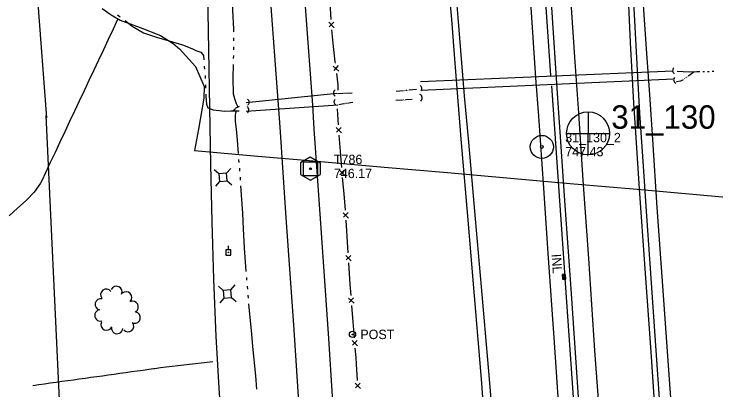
# Model space of a CAD drawing. Extents: x 589250 to 1188077, y 162953 to 363065.
# Drawn here: x 593773.6 to 594223.8, y 172497 to 172737.9 of the extents above; entities that cross this region are included whole.
import ezdxf

# ---------------------------------------------------------------- set-up
doc = ezdxf.new("R2010")
doc.units = 0
for name, color, linetype in [('E_DRN', 7, 'Continuous'), ('E_DRN_DrainTile', 7, 'Continuous'), ('E_DRN_Pipe', 7, 'Continuous'), ('E_DRN_SS_UG', 7, 'Continuous'), ('E_DRN_Text', 7, 'Continuous'), ('E_FEN_P', 7, 'Continuous'), ('E_LAND_TreeLine_P', 7, 'Continuous'), ('E_MAP_Control', 7, 'Continuous'), ('E_MAP_Limits', 7, 'Continuous'), ('E_MAP_PassPoints', 7, 'Continuous'), ('E_MAP_PhotoCenter', 7, 'Continuous'), ('E_MISCPROP', 7, 'Continuous'), ('E_RDWY', 7, 'Continuous'), ('E_RDWY_Gravel', 7, 'Continuous'), ('E_UTL_AG_Bold', 7, 'Continuous'), ('E_UTL_EPowerPole', 7, 'Continuous'), ('E_WAL', 7, 'Continuous'), ('E_WTR_FlowLine', 7, 'Continuous')]:
    doc.layers.add(name, color=color, linetype=linetype)

msp = doc.modelspace()

# ---------------------------------------------------------------- linework, layer by layer
at = {"layer": 'E_DRN'}
for p, q in [((594127.19, 172571.11), (594125.2, 172570.98)), ((594125.2, 172570.98), (594125.39, 172567.99)), ((594125.26, 172569.99), (594127.26, 172570.11)), ((594126.39, 172568.05), (594126.19, 172571.05)), ((594127.38, 172568.12), (594127.19, 172571.11)), ((594125.32, 172568.99), (594127.32, 172569.12)), ((594125.39, 172567.99), (594127.38, 172568.12))]:
    msp.add_line(p, q, dxfattribs=at)
for centre, radius, start, end in [((594198.32, 172701.63), 2.34, 131.1922, 237.4524), ((594198.89, 172695.73), 2.27, 141.862, 248.1222), ((594033.01, 172690.17), 2.09, 316.5719, 62.8321), ((593980.99, 172687.34), 2.54, 127.8258, 234.086), ((593921.97, 172681.39), 2.38, 307.8258, 54.086), ((593980.8, 172681.59), 2.07, 132.2245, 238.4847), ((594032.61, 172684.07), 2.72, 314.5356, 60.7958), ((593921.8, 172676.47), 2.38, 311.6398, 57.9)]:
    msp.add_arc(centre, radius, start, end, dxfattribs=at)
at = {"layer": 'E_DRN_DrainTile'}
for points in [[(593897.72, 172751.54), (593898.36, 172714.83), (593898.93, 172678.11), (593899.54, 172641.39), (593900.34, 172604.68), (593901.46, 172567.99), (593903.04, 172531.34), (593905.22, 172494.73), (593906.8, 172473.69), (593908.07, 172458.17), (593911.04, 172421.61), (593914.01, 172385.06), (593916.99, 172348.5), (593919.96, 172311.94), (593922.93, 172275.39), (593925.91, 172238.83), (593928.88, 172202.28)], [(593830.1, 172741.37), (593835.95, 172737.31), (593841.72, 172734.01), (593854.48, 172729.18), (593867.49, 172724.11), (593875.56, 172719.02), (593879.65, 172715.58), (593889.87, 172704.25), (593895.41, 172691.4), (593895.37, 172683.98), (593894.25, 172677.8), (593891.77, 172664.13), (593889.28, 172650.45), (593889.28, 172650.45), (593889.28, 172650.45)], [(593840.14, 172734.74), (593837.04, 172728.16), (593833.95, 172721.59), (593830.85, 172715.01), (593827.76, 172708.44), (593824.66, 172701.86), (593821.57, 172695.29), (593818.48, 172688.71), (593815.38, 172682.13), (593812.29, 172675.56), (593809.19, 172668.98), (593806.1, 172662.41), (593803, 172655.83), (593799.91, 172649.26), (593796.82, 172642.68), (593793.72, 172636.11), (593791.37, 172631.12), (593790.58, 172629.56), (593786.45, 172623.68), (593781.34, 172618.44), (593775.8, 172613.52), (593770.36, 172608.57)], [(593840.14, 172734.74), (593837.04, 172728.16), (593833.95, 172721.59), (593830.85, 172715.01), (593827.76, 172708.44), (593824.66, 172701.86), (593821.57, 172695.29), (593818.48, 172688.71), (593815.38, 172682.13), (593812.29, 172675.56), (593809.19, 172668.98), (593806.1, 172662.41), (593803, 172655.83), (593799.91, 172649.26), (593796.82, 172642.68), (593793.72, 172636.11), (593791.37, 172631.12), (593790.58, 172629.56), (593786.45, 172623.68), (593781.34, 172618.44), (593775.8, 172613.52), (593770.36, 172608.57)], [(593889.28, 172650.45), (593929.83, 172646.9), (593970.38, 172643.35), (594010.93, 172639.81), (594051.48, 172636.26), (594092.03, 172632.71), (594132.58, 172629.16), (594173.13, 172625.61), (594213.68, 172622.07), (594254.23, 172618.52), (594294.78, 172614.97), (594335.33, 172611.42), (594375.88, 172607.87), (594416.43, 172604.33), (594452.4, 172601.18), (594456.95, 172600.68), (594494.43, 172588.87), (594528.02, 172566.6), (594559.18, 172537.96)], [(593889.28, 172650.45), (593929.83, 172646.9), (593970.38, 172643.35), (594010.93, 172639.81), (594051.48, 172636.26), (594092.03, 172632.71), (594132.58, 172629.16), (594173.13, 172625.61), (594213.68, 172622.07), (594254.23, 172618.52), (594294.78, 172614.97), (594335.33, 172611.42), (594375.88, 172607.87), (594416.43, 172604.33), (594452.4, 172601.18), (594456.95, 172600.68), (594494.43, 172588.87), (594528.02, 172566.6), (594559.18, 172537.96)], [(593785.65, 172499.99), (593789.37, 172500.51), (593793.09, 172501.02), (593796.81, 172501.54), (593800.53, 172502.06), (593804.25, 172502.57), (593807.97, 172503.09), (593811.69, 172503.61), (593815.41, 172504.13), (593819.13, 172504.64), (593822.85, 172505.16), (593826.57, 172505.68), (593830.29, 172506.19), (593834.01, 172506.71), (593837.73, 172507.23), (593841.45, 172507.74), (593845.17, 172508.26), (593848.89, 172508.78), (593852.62, 172509.29), (593856.34, 172509.81), (593860.06, 172510.33), (593862.99, 172510.74), (593863.79, 172510.84), (593867.52, 172511.34), (593871.24, 172511.82), (593874.97, 172512.28), (593878.7, 172512.72), (593882.43, 172513.16), (593886.16, 172513.58), (593889.9, 172514.01), (593893.63, 172514.43), (593897.36, 172514.87), (593901.09, 172515.31), (593901.09, 172515.31), (593901.09, 172515.31)]]:
    msp.add_lwpolyline(points, dxfattribs=at)
at = {"layer": 'E_DRN_Pipe'}
for p, q in [((594117.95, 172698.49), (594099.27, 172967.03)), ((594034.19, 172694.63), (594196.39, 172701.51)), ((594196.66, 172696.18), (594034.43, 172688.97)), ((593922.5, 172681.23), (593980.52, 172687.25)), ((593922.54, 172675.76), (593981.32, 172679.71)), ((594147.67, 172271.34), (594126.99, 172568.64))]:
    msp.add_line(p, q, dxfattribs=at)
msp.add_lwpolyline([(594163.21, 172899.17), (594166.48, 172833.15), (594167.75, 172807.22), (594168.84, 172784.41), (594170.33, 172757.55), (594171.64, 172729.6), (594173.17, 172701.66), (594174.76, 172674.39), (594177.1, 172640.49), (594178.95, 172611.66), (594181.35, 172577.92), (594185.75, 172513.06), (594188.07, 172482.37), (594189.42, 172460.9)], dxfattribs=at)
at = {"layer": 'E_DRN_SS_UG'}
msp.add_line((594126.94, 172569.34), (594118.41, 172691.87), dxfattribs=at)
at = {"layer": 'E_FEN_P'}
for p, q in [((593976.02, 172745.13), (593976.75, 172734.41)), ((593975.37, 172732.66), (593978.88, 172729.15)), ((593978.63, 172732.71), (593975.64, 172729.68)), ((593977.21, 172727.78), (593977.5, 172723.56)), ((593977.5, 172723.56), (593978.25, 172717.08)), ((593978.25, 172717.08), (593979.38, 172707.28)), ((593979.38, 172707.28), (593979.49, 172706.41)), ((593978.2, 172704.58), (593981.9, 172701.27)), ((593981.45, 172704.82), (593978.64, 172701.63)), ((593980.31, 172699.81), (593981.23, 172692.46)), ((593981.23, 172692.46), (593981.29, 172689.12)), ((593980.75, 172677.24), (593981.49, 172666.82)), ((593980.15, 172665.11), (593983.57, 172661.7)), ((593983.32, 172665.17), (593980.42, 172662.22)), ((593981.95, 172660.36), (593982.7, 172649.94)), ((593982.7, 172649.94), (593983.09, 172644.41)), ((593983.09, 172644.41), (593983.52, 172639.52)), ((593982.21, 172637.79), (593985.68, 172634.44)), ((593985.38, 172637.9), (593982.53, 172634.9)), ((593984.09, 172633.08), (593985.01, 172622.67)), ((593985.01, 172622.67), (593985.93, 172612.26)), ((593984.61, 172610.53), (593988.09, 172607.18)), ((593987.78, 172610.64), (593984.93, 172607.64)), ((593986.44, 172605.81), (593987.08, 172595.38)), ((593987.08, 172595.38), (593987.71, 172584.95)), ((593986.34, 172583.25), (593989.73, 172579.81)), ((593989.52, 172583.28), (593986.58, 172580.36)), ((593988.1, 172578.49), (593988.73, 172568.06)), ((593988.73, 172568.06), (593988.93, 172564.77)), ((593988.93, 172564.77), (593989.5, 172557.63)), ((593988.17, 172555.91), (593991.62, 172552.54)), ((593991.35, 172556), (593988.47, 172553.02)), ((593990.02, 172551.19), (593990.86, 172540.77)), ((593990.86, 172540.77), (593991.7, 172530.35)), ((593990.37, 172528.63), (593993.82, 172525.26)), ((593993.54, 172528.72), (593990.67, 172525.74)), ((593992.22, 172523.9), (593992.71, 172517.81)), ((593992.71, 172517.81), (593993, 172513.48)), ((593993, 172513.48), (593993.72, 172503.05)), ((593992.36, 172501.35), (593995.78, 172497.93)), ((593995.54, 172501.4), (593992.63, 172498.46))]:
    msp.add_line(p, q, dxfattribs=at)
at = {"layer": 'E_LAND_TreeLine_P'}
for centre, start, end in [((593832.72, 172558), 36.8561, 216.8561), ((593839.23, 172559.88), 336.1583, 156.1583), ((593845.47, 172556.35), 313.8665, 133.8665), ((593829.24, 172551.81), 76.566, 256.566), ((593849.65, 172550.26), 297.1673, 117.1673), ((593829, 172544.75), 104.6385, 284.6385), ((593850.92, 172543.36), 259.2923, 79.2923), ((593832.89, 172538.92), 156.3745, 336.3745), ((593846.73, 172537.87), 220.0747, 40.0747), ((593839.73, 172536.7), 175.4078, 355.4078)]:
    msp.add_arc(centre, 3.64, start, end, dxfattribs=at)
at = {"layer": 'E_MAP_Control'}
for p, q in [((593959.18, 172634.27), (593959.18, 172643.27)), ((593959.18, 172643.27), (593968.18, 172643.27)), ((593959.18, 172634.27), (593959.18, 172643.27)), ((593959.18, 172643.27), (593968.18, 172643.27)), ((593968.18, 172643.27), (593968.18, 172634.27)), ((593968.18, 172643.27), (593968.18, 172634.27)), ((593968.18, 172634.27), (593959.18, 172634.27)), ((593968.18, 172634.27), (593959.18, 172634.27))]:
    msp.add_line(p, q, dxfattribs=at)
msp.add_lwpolyline([(593957.27, 172642.53), (593957.27, 172635.14), (593963.73, 172631.42), (593970.12, 172635.08), (593970.12, 172642.41), (593963.6, 172646.13)], close=True, dxfattribs=at)
msp.add_lwpolyline([(593957.27, 172642.53), (593957.27, 172635.14), (593963.73, 172631.42), (593970.12, 172635.08), (593970.12, 172642.41), (593963.6, 172646.13)], close=True, dxfattribs=at)
msp.add_circle((593963.68, 172638.77), 0.546, dxfattribs=at)
msp.add_circle((593963.68, 172638.77), 0.546, dxfattribs=at)
at = {"layer": 'E_MAP_Limits'}
for p, q in [((593788.54, 172747.67), (593794.28, 172671.36)), ((593809.24, 172353.09), (593794.17, 172672.82))]:
    msp.add_line(p, q, dxfattribs=at)
at = {"layer": 'E_MAP_PassPoints'}
for radius in [7.38, 7.38, 0.945, 0.945]:
    msp.add_circle((594112.08, 172652.77), radius, dxfattribs=at)
at = {"layer": 'E_MAP_PhotoCenter'}
for p, q in [((594141.72, 172675.22), (594141.65, 172647.81)), ((594141.72, 172675.22), (594141.65, 172647.81)), ((594128.03, 172661.41), (594155.49, 172661.4)), ((594128.03, 172661.41), (594155.49, 172661.4))]:
    msp.add_line(p, q, dxfattribs=at)
msp.add_circle((594141.77, 172661.42), 13.78, dxfattribs=at)
msp.add_circle((594141.77, 172661.42), 13.78, dxfattribs=at)
at = {"layer": 'E_MISCPROP'}
for radius in [2, 0.25]:
    msp.add_circle((593990.66, 172532.63), radius, dxfattribs=at)
at = {"layer": 'E_RDWY'}
for p, q in [((594052.77, 172797.07), (594058.17, 172735.71)), ((593958.7, 172764.44), (593962.07, 172719.65)), ((594166.65, 172762.38), (594168.81, 172719.74)), ((593937.54, 172753.91), (593941.15, 172705.31)), ((594104.55, 172749.92), (594108.09, 172696.97)), ((594130.19, 172752.45), (594133.09, 172710.31)), ((594058.17, 172735.71), (594062.29, 172685.58)), ((593962.07, 172719.65), (593965, 172679.56)), ((594168.81, 172719.74), (594170.92, 172680.85)), ((594133.09, 172710.31), (594135.61, 172674.34)), ((593941.15, 172705.31), (593943.97, 172665.31)), ((594108.09, 172696.97), (594109.91, 172672.47)), ((594062.29, 172685.58), (594064.98, 172655.75)), ((593965, 172679.56), (593965.95, 172664.39)), ((594170.92, 172680.85), (594172.2, 172661.96)), ((594135.61, 172674.34), (594138.45, 172631.53)), ((594109.91, 172672.47), (594113.21, 172626.32)), ((593943.97, 172665.31), (593947.99, 172607.25)), ((593965.95, 172664.39), (593970.15, 172603.69)), ((594172.2, 172661.96), (594174.52, 172625.81)), ((594064.98, 172655.75), (594069.23, 172606.68)), ((594138.45, 172631.53), (594141.98, 172581.25)), ((594113.21, 172626.32), (594116.03, 172584.77)), ((594174.52, 172625.81), (594178.23, 172574.59)), ((593947.99, 172607.25), (593952.7, 172538.72)), ((594069.23, 172606.68), (594073.09, 172563.02)), ((593970.15, 172603.69), (593975.17, 172529.92)), ((594116.03, 172584.77), (594119.96, 172527.51)), ((594141.98, 172581.25), (594145.93, 172522.41)), ((594178.23, 172574.59), (594181.99, 172521.46)), ((594073.09, 172563.02), (594077.76, 172511.48)), ((593952.7, 172538.72), (593957.43, 172468.93)), ((593975.17, 172529.92), (593981.09, 172440.94)), ((594119.96, 172527.51), (594123.35, 172476.44)), ((594145.93, 172522.41), (594148.46, 172487.84)), ((594181.99, 172521.46), (594185.37, 172472.13)), ((594077.76, 172511.48), (594082.45, 172456.36))]:
    msp.add_line(p, q, dxfattribs=at)
at = {"layer": 'E_RDWY_Gravel'}
for p, q in [((594051.2, 172767.83), (594054.07, 172734.33)), ((594176.86, 172746.68), (594179, 172715.65)), ((594054.07, 172734.33), (594056.35, 172706.36)), ((594179, 172715.65), (594181.09, 172686.25)), ((594056.35, 172706.36), (594058.59, 172676.7)), ((594181.09, 172686.25), (594182.98, 172657.59)), ((594058.59, 172676.7), (594060.31, 172655.15)), ((594060.29, 172655.39), (594064.41, 172608.3)), ((594182.98, 172657.59), (594185.75, 172613.84)), ((594185.75, 172613.84), (594189.99, 172557.7)), ((594064.41, 172608.3), (594068.6, 172557.39)), ((594068.6, 172557.39), (594073.31, 172501.42)), ((594189.99, 172557.7), (594194.84, 172488.87)), ((594073.31, 172501.42), (594077.16, 172452.26))]:
    msp.add_line(p, q, dxfattribs=at)
at = {"layer": 'E_UTL_AG_Bold'}
for p, q in [((593904.93, 172635.55), (593901.89, 172638.15)), ((593909.92, 172635.94), (593912.52, 172638.98)), ((593909.92, 172635.94), (593904.93, 172635.55)), ((593904.93, 172635.55), (593905.32, 172630.57)), ((593910.31, 172630.96), (593909.92, 172635.94)), ((593905.32, 172630.57), (593902.72, 172627.53)), ((593905.32, 172630.57), (593910.31, 172630.96)), ((593910.31, 172630.96), (593913.35, 172628.36)), ((593907.71, 172560.86), (593904.67, 172563.46)), ((593912.69, 172561.25), (593907.71, 172560.86)), ((593907.71, 172560.86), (593908.1, 172555.88)), ((593912.69, 172561.25), (593915.29, 172564.29)), ((593913.08, 172556.27), (593912.69, 172561.25)), ((593908.1, 172555.88), (593905.5, 172552.84)), ((593908.1, 172555.88), (593913.08, 172556.27)), ((593913.08, 172556.27), (593916.12, 172553.67))]:
    msp.add_line(p, q, dxfattribs=at)
at = {"layer": 'E_UTL_EPowerPole'}
for points in [[(593911.02, 172586.84), (593911.02, 172589.48)], [(593912.69, 172586.84), (593909.34, 172586.84)], [(593909.34, 172586.84), (593909.34, 172583.48)], [(593909.34, 172583.48), (593912.69, 172583.48)], [(593912.69, 172583.48), (593912.69, 172586.84)]]:
    msp.add_lwpolyline(points, dxfattribs=at)
msp.add_circle((593911.05, 172585.16), 0.217, dxfattribs=at)
at = {"layer": 'E_WAL'}
for p, q in [((594116.59, 172766.21), (594121.38, 172696.7)), ((594121.38, 172696.7), (594123.26, 172668.29)), ((594123.24, 172668.55), (594126.73, 172615.21)), ((594126.73, 172615.21), (594130.78, 172561.83)), ((594130.78, 172561.83), (594136.11, 172481.46))]:
    msp.add_line(p, q, dxfattribs=at)
at = {"layer": 'E_WTR_FlowLine'}
for p, q in [((593912.83, 172754.11), (593914.37, 172728.22)), ((593839.94, 172737.32), (593841.54, 172736.1)), ((593844.76, 172733.67), (593849.35, 172730.18)), ((593849.35, 172730.18), (593856.66, 172725.86)), ((593914.37, 172728.22), (593914.36, 172726.49)), ((593856.66, 172725.86), (593865.59, 172722.84)), ((593865.59, 172722.84), (593870.91, 172721.28)), ((593870.91, 172721.28), (593881.54, 172718.15)), ((593914.32, 172722.67), (593914.3, 172720.76)), ((593881.54, 172718.15), (593887.67, 172715.84)), ((593887.67, 172715.84), (593890.1, 172714.62)), ((593890.1, 172714.62), (593893.42, 172713.4)), ((593914.27, 172716.95), (593914.25, 172715.04)), ((593893.42, 172713.4), (593894.98, 172711.4)), ((593894.98, 172711.4), (593895.22, 172708.6)), ((593914.22, 172711.22), (593914.2, 172709.32)), ((593914.11, 172705.5), (593913.87, 172697.12)), ((593895.57, 172704.59), (593895.75, 172702.58)), ((594198.87, 172701.2), (594206.5, 172700.91)), ((594206.38, 172698.46), (594209.71, 172700.97)), ((594206.5, 172700.91), (594211.45, 172700.99)), ((594211.45, 172700.99), (594213.38, 172701.03)), ((594215.39, 172701.06), (594215.58, 172701.06)), ((594215.58, 172701.06), (594216.39, 172701.08)), ((594218.39, 172701.11), (594218.98, 172701.12)), ((594218.98, 172701.12), (594219.39, 172701.14)), ((594221.39, 172701.26), (594222.39, 172701.31)), ((593896.1, 172698.56), (593896.23, 172697.08)), ((593896.23, 172697.08), (593896.25, 172696.55)), ((593913.87, 172697.12), (593914.17, 172686.71)), ((594201.33, 172695.1), (594203.01, 172696.02)), ((594203.58, 172696.34), (594203.83, 172696.55)), ((594204.34, 172696.96), (594204.59, 172697.17)), ((594205.1, 172697.58), (594205.37, 172697.76)), ((594205.91, 172698.13), (594206.38, 172698.46)), ((593896.36, 172692.52), (593896.41, 172690.5)), ((594198.55, 172694.67), (594201.33, 172695.1)), ((593980.99, 172687.01), (593984.39, 172687.14)), ((593984.86, 172687.16), (593985.09, 172687.16)), ((593985.56, 172687.18), (593985.79, 172687.19)), ((593986.26, 172687.21), (593986.5, 172687.22)), ((593986.97, 172687.24), (593990.36, 172687.37)), ((594023.44, 172688.71), (594018.7, 172688.25)), ((594024.42, 172688.8), (594024.09, 172688.77)), ((594025.4, 172688.89), (594025.07, 172688.86)), ((594026.38, 172688.99), (594026.06, 172688.96)), ((594031.78, 172689.5), (594027.04, 172689.05)), ((593896.52, 172686.47), (593896.56, 172685.02)), ((593896.56, 172685.02), (593897.02, 172680.21)), ((593914.17, 172686.71), (593914.86, 172683.68)), ((593914.86, 172683.68), (593916.05, 172680.65)), ((594022.26, 172682.72), (594018.49, 172682.48)), ((594023.04, 172682.78), (594022.78, 172682.76)), ((594023.82, 172682.83), (594023.56, 172682.81)), ((594024.6, 172682.88), (594024.34, 172682.86)), ((594028.89, 172683.16), (594025.12, 172682.91)), ((593897.02, 172680.21), (593897.95, 172677.81)), ((593916.05, 172680.65), (593917.14, 172678.42)), ((593916.05, 172677.9), (593916.16, 172677.95)), ((593916.4, 172678.07), (593917.36, 172678.52)), ((593917.36, 172678.52), (593918.11, 172678.91)), ((593981.83, 172680.01), (593985.08, 172680.51)), ((593985.52, 172680.58), (593985.75, 172680.61)), ((593986.2, 172680.68), (593986.42, 172680.72)), ((593986.87, 172680.78), (593987.09, 172680.82)), ((593987.54, 172680.89), (593989.33, 172681.16)), ((593989.33, 172681.16), (593990.77, 172681.5)), ((593897.95, 172677.81), (593901.27, 172676.6)), ((593901.27, 172676.6), (593905.09, 172676.03)), ((593905.09, 172676.03), (593908.64, 172675.71)), ((593908.64, 172675.71), (593912.58, 172675.77)), ((593912.58, 172675.77), (593914.35, 172675.8)), ((593913.97, 172675.8), (593915.3, 172677.16)), ((593914.35, 172675.8), (593918.03, 172675.86)), ((593915.48, 172677.35), (593915.57, 172677.45)), ((593915.63, 172672.83), (593915.83, 172674.53)), ((593915.75, 172677.64), (593915.85, 172677.73)), ((593915.83, 172674.53), (593916.18, 172675.83)), ((593915.5, 172671.06), (593915.63, 172672.83)), ((593915.59, 172669.14), (593915.5, 172671.06)), ((593916.23, 172664.21), (593915.59, 172669.14)), ((593916.82, 172657), (593916.23, 172664.21)), ((593917.52, 172648.54), (593916.82, 172657)), ((593917.99, 172642.87), (593917.84, 172644.76)), ((593918.46, 172637.21), (593918.31, 172639.1)), ((593918.87, 172631.54), (593918.74, 172633.43)), ((593920.34, 172610.32), (593919.13, 172627.76)), ((593920.77, 172600.35), (593920.34, 172610.32)), ((593921.31, 172588.07), (593920.77, 172600.35)), ((593922.51, 172572.94), (593921.31, 172588.07)), ((593922.96, 172567.28), (593922.81, 172569.17)), ((593923.41, 172561.61), (593923.26, 172563.5)), ((593923.92, 172555.95), (593923.75, 172557.84)), ((593926.01, 172532.78), (593924.26, 172552.18)), ((593926.78, 172524.83), (593926.01, 172532.78)), ((593928.58, 172506.06), (593926.78, 172524.83)), ((593929.37, 172497.48), (593928.58, 172506.06))]:
    msp.add_line(p, q, dxfattribs=at)

# ---------------------------------------------------------------- texts
at = {"layer": 'E_DRN_Text'}
msp.add_text('INL', height=6, rotation=273.6668, dxfattribs=at).set_placement((594118.33, 172584.01))
at = {"layer": 'E_MAP_Control'}
for s, p in [('T786', (593978.69, 172641.77)), ('T786', (593978.69, 172641.77)), ('746.17', (593978.69, 172632.77)), ('746.17', (593978.69, 172632.77))]:
    msp.add_text(s, height=6, dxfattribs=at).set_placement(p)
at = {"layer": 'E_MAP_PassPoints'}
for s, p in [('31_130_2', (594127.08, 172655.75)), ('31_130_2', (594127.08, 172655.75)), ('747.43', (594127.08, 172646.75)), ('747.43', (594127.08, 172646.75))]:
    msp.add_text(s, height=6, dxfattribs=at).set_placement(p)
at = {"layer": 'E_MAP_PhotoCenter'}
msp.add_text('31_130', height=15, dxfattribs=at).set_placement((594156.62, 172664.4))
msp.add_text('31_130', height=15, dxfattribs=at).set_placement((594156.62, 172664.4))
at = {"layer": 'E_MISCPROP'}
msp.add_text('POST', height=6, dxfattribs=at).set_placement((593995.66, 172529.63))

doc.saveas('drawing.dxf')
